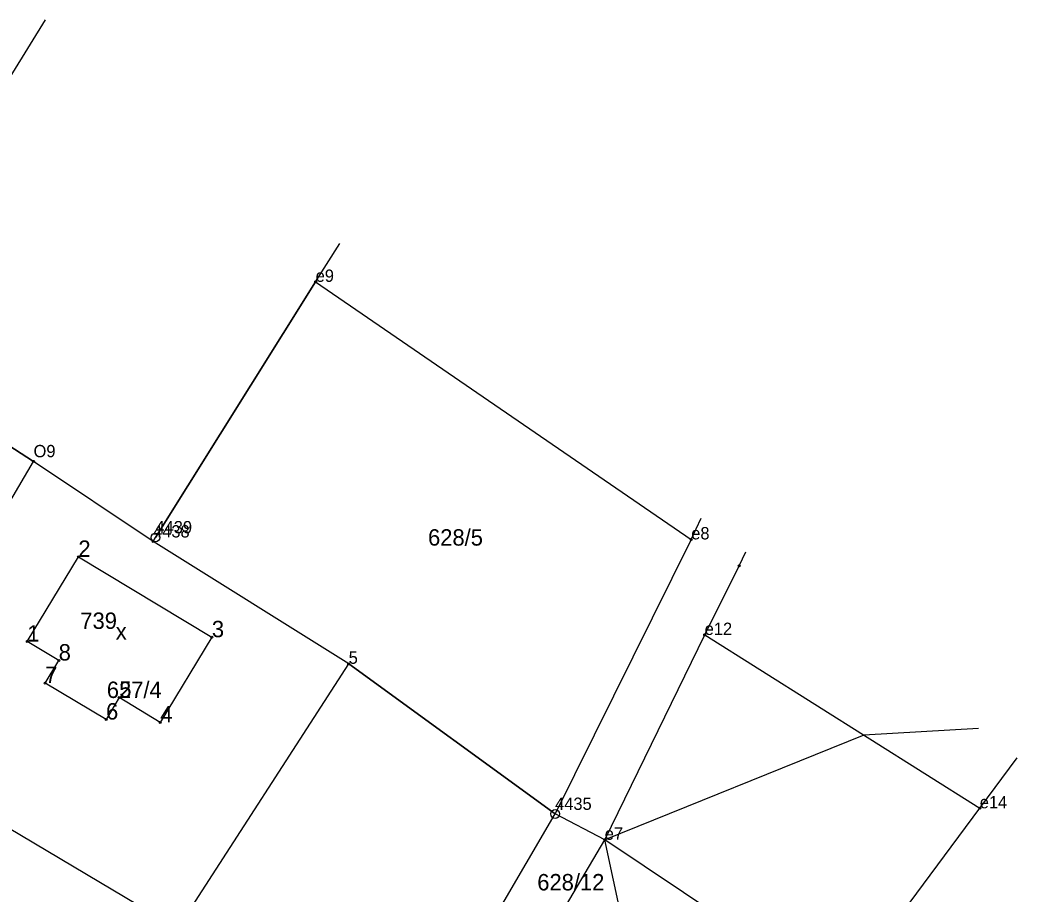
# Model space of a CAD drawing. Extents: x 7465393 to 7466459, y 5491258 to 5492404.
# Drawn here: x 7466088.4 to 7466179.6, y 5491575.9 to 5491655.9 of the extents above; entities that cross this region are included whole.
import ezdxf

# ---------------------------------------------------------------- set-up
doc = ezdxf.new("R2010")
doc.units = 0
for name, color, linetype in [('202-punkt graniczny', 7, 'Continuous'), ('202-punkt graniczny-Atr103', 7, 'Continuous'), ('203-punkt graniczny', 7, 'Continuous'), ('203-punkt graniczny-Atr103', 7, 'Continuous'), ('211-numer działki ewidencyjnej', 7, 'Continuous'), ('217-kontur klasyfikacyjny', 7, 'Continuous'), ('218-kontur użytku gruntowego', 7, 'Continuous'), ('219-działka ewidencyjna', 7, 'Continuous'), ('312-budynek ewidencyjny', 7, 'Continuous'), ('312-oznaczenie budynku ewidencyjnego', 7, 'Continuous'), ('312-oznaczenie budynku ewidencyjnego-Atr117', 7, 'Continuous'), ('Punkt budynku', 7, 'Continuous'), ('Punkt budynku-Atr104', 7, 'Continuous')]:
    doc.layers.add(name, color=color, linetype=linetype)

# ---------------------------------------------------------------- blocks, each defined once
blk = doc.blocks.new('203')
blk.add_circle((0, 0), 0.09)
blk = doc.blocks.new('202')
blk.add_circle((0, 0), 0.4)
blk = doc.blocks.new('PUNKTBUD')
blk.add_circle((0, 0), 0.09)

msp = doc.modelspace()

# ---------------------------------------------------------------- linework, layer by layer
at = {"layer": '217-kontur klasyfikacyjny'}
for points in [[(7466089.63, 5491615.53), (7466072.57, 5491626.54)], [(7466100.56, 5491608.19), (7466089.63, 5491615.53)], [(7466118.45, 5491597.01), (7466100.56, 5491608.19)], [(7466137.33, 5491583.27), (7466118.45, 5491597.01)], [(7466165.58, 5491590.47), (7466141.87, 5491580.91)], [(7466176.041, 5491591.095), (7466165.58, 5491590.47)], [(7466141.87, 5491580.91), (7466137.33, 5491583.27)], [(7466149.1, 5491547.26), (7466141.87, 5491580.91)]]:
    msp.add_lwpolyline(points, dxfattribs=at)
at = {"layer": '218-kontur użytku gruntowego'}
for points in [[(7466115.43, 5491631.95), (7466117.64, 5491635.453)], [(7466100.78, 5491608.57), (7466115.43, 5491631.95)], [(7466100.56, 5491608.19), (7466100.78, 5491608.57)], [(7466118.45, 5491597.01), (7466100.56, 5491608.19)], [(7466137.33, 5491583.27), (7466118.45, 5491597.01)], [(7466141.87, 5491580.91), (7466137.33, 5491583.27)], [(7466149.1, 5491547.26), (7466141.87, 5491580.91)], [(7466163.36, 5491566.5), (7466141.87, 5491580.91)]]:
    msp.add_lwpolyline(points, dxfattribs=at)
at = {"layer": '219-działka ewidencyjna'}
for points in [[(7466073.64, 5491628.25), (7466090.709, 5491655.909)], [(7466115.43, 5491631.95), (7466117.64, 5491635.453)], [(7466115.43, 5491631.95), (7466100.78, 5491608.57)], [(7466115.43, 5491631.95), (7466149.78, 5491608.39)], [(7466072.57, 5491626.54), (7466089.63, 5491615.53)], [(7466074.24, 5491589.32), (7466089.63, 5491615.53)], [(7466100.56, 5491608.19), (7466089.63, 5491615.53)], [(7466149.78, 5491608.39), (7466150.695, 5491610.346)], [(7466100.56, 5491608.19), (7466100.78, 5491608.57)], [(7466118.45, 5491597.01), (7466100.56, 5491608.19)], [(7466149.78, 5491608.39), (7466137.33, 5491583.27)], [(7466154.16, 5491605.97), (7466154.762, 5491607.257)], [(7466151.01, 5491599.65), (7466154.16, 5491605.97)], [(7466141.87, 5491580.91), (7466151.01, 5491599.65)], [(7466151.01, 5491599.65), (7466176.17, 5491583.79)], [(7466102.82, 5491572.78), (7466118.45, 5491597.01)], [(7466118.45, 5491597.01), (7466137.33, 5491583.27)], [(7466176.17, 5491583.79), (7466179.58, 5491588.407)], [(7466078.85, 5491587.02), (7466102.82, 5491572.78)], [(7466097.56, 5491515.12), (7466137.33, 5491583.27)], [(7466149.1, 5491547.26), (7466176.17, 5491583.79)], [(7466128.99, 5491559.04), (7466141.87, 5491580.91)]]:
    msp.add_lwpolyline(points, dxfattribs=at)
at = {"layer": '312-budynek ewidencyjny'}
for points in [[(7466089.06, 5491599.04), (7466093.73, 5491606.79)], [(7466093.73, 5491606.79), (7466105.94, 5491599.44)], [(7466091.93, 5491597.31), (7466089.06, 5491599.04)], [(7466105.94, 5491599.44), (7466101.22, 5491591.64)], [(7466090.69, 5491595.25), (7466091.93, 5491597.31)], [(7466096.26, 5491591.91), (7466090.69, 5491595.25)], [(7466097.47, 5491593.92), (7466096.26, 5491591.91)], [(7466101.22, 5491591.64), (7466097.47, 5491593.92)]]:
    msp.add_lwpolyline(points, dxfattribs=at)

# ---------------------------------------------------------------- block references
at = {"layer": '202-punkt graniczny'}
for p in [(7466100.78, 5491608.57), (7466137.33, 5491583.27)]:
    msp.add_blockref('202', p, dxfattribs=at)
at = {"layer": '203-punkt graniczny'}
for p in [(7466115.43, 5491631.95), (7466089.63, 5491615.53), (7466100.56, 5491608.19), (7466149.78, 5491608.39), (7466154.16, 5491605.97), (7466151.01, 5491599.65), (7466118.45, 5491597.01), (7466176.17, 5491583.79), (7466141.87, 5491580.91)]:
    msp.add_blockref('203', p, dxfattribs=at)
at = {"layer": 'Punkt budynku'}
for p in [(7466093.73, 5491606.79), (7466105.94, 5491599.44), (7466089.06, 5491599.04), (7466091.93, 5491597.31), (7466090.69, 5491595.25), (7466097.47, 5491593.92), (7466096.26, 5491591.91), (7466101.22, 5491591.64)]:
    msp.add_blockref('PUNKTBUD', p, dxfattribs=at)

# ---------------------------------------------------------------- texts
at = {"layer": '202-punkt graniczny-Atr103'}
for s, p in [('4439', (7466100.78, 5491608.945)), ('4435', (7466137.33, 5491583.645))]:
    msp.add_text(s, height=1.125, dxfattribs=at).set_placement(p)
at = {"layer": '203-punkt graniczny-Atr103'}
for s, p in [('e9', (7466115.43, 5491631.95)), ('O9', (7466089.63, 5491615.905)), ('4438', (7466100.56, 5491608.565)), ('e8', (7466149.78, 5491608.39)), ('e12', (7466151.01, 5491599.65)), ('5', (7466118.45, 5491597.01)), ('e14', (7466176.17, 5491583.79)), ('e7', (7466141.87, 5491580.91))]:
    msp.add_text(s, height=1.125, dxfattribs=at).set_placement(p)
at = {"layer": '211-numer działki ewidencyjnej'}
for s, p in [('628/5', (7466125.71, 5491607.82)), ('627/4', (7466096.33, 5491593.88)), ('628/12', (7466135.7, 5491576.28))]:
    msp.add_text(s, height=1.5, dxfattribs=at).set_placement(p)
at = {"layer": '312-oznaczenie budynku ewidencyjnego'}
msp.add_text('739', height=1.5, dxfattribs=at).set_placement((7466093.91, 5491600.2))
at = {"layer": '312-oznaczenie budynku ewidencyjnego-Atr117'}
msp.add_text('x', height=1.5, dxfattribs=at).set_placement((7466097.146, 5491599.22))
at = {"layer": 'Punkt budynku-Atr104'}
for s, p in [('2', (7466093.73, 5491606.79)), ('1', (7466089.06, 5491599.04)), ('3', (7466105.94, 5491599.44)), ('8', (7466091.93, 5491597.31)), ('7', (7466090.69, 5491595.25)), ('5', (7466097.47, 5491593.92)), ('6', (7466096.26, 5491591.91)), ('4', (7466101.22, 5491591.64))]:
    msp.add_text(s, height=1.5, dxfattribs=at).set_placement(p)

doc.saveas('drawing.dxf')
